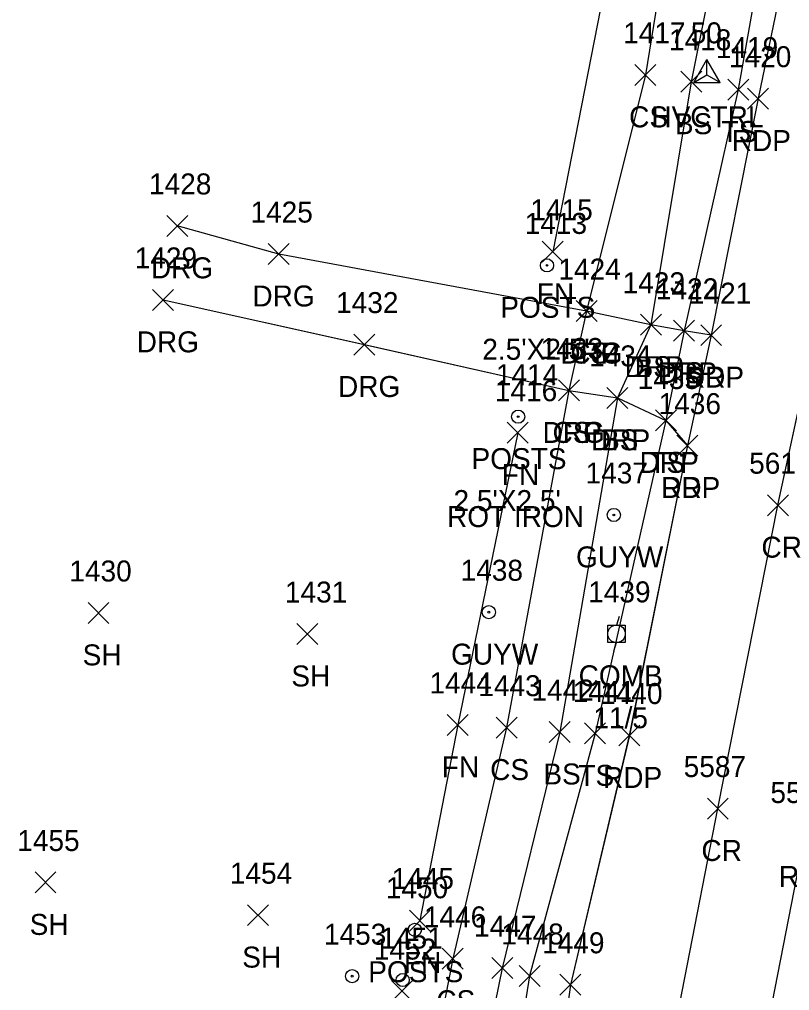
# Model space of a CAD drawing. Extents: x 1554668 to 1563881, y 831386 to 834374.
# Drawn here: x 1561703.5 to 1561777, y 833208.3 to 833300.9 of the extents above; entities that cross this region are included whole.
import ezdxf

# ---------------------------------------------------------------- set-up
doc = ezdxf.new("R2010")
doc.units = 0
for name, color, linetype in [('C_A', 7, 'Continuous'), ('C_I', 7, 'Continuous'), ('CPSM', 7, 'Continuous'), ('L_A', 7, 'Continuous'), ('L_C', 7, 'Continuous'), ('L_I', 7, 'Continuous'), ('L_TIC', 7, 'Continuous'), ('LELB', 7, 'Continuous'), ('LFNC', 7, 'Continuous'), ('LPST', 7, 'Continuous'), ('P_A', 7, 'Continuous'), ('P_I', 7, 'Continuous'), ('P_TIC', 7, 'Continuous'), ('PET', 7, 'Continuous'), ('PRC', 7, 'Continuous'), ('R_A', 7, 'Continuous'), ('R_I', 7, 'Continuous'), ('R_TIC', 7, 'Continuous'), ('RDG', 7, 'Continuous'), ('RDP', 7, 'Continuous'), ('U_A', 7, 'Continuous'), ('U_C', 7, 'Continuous'), ('U_I', 7, 'Continuous'), ('UP', 7, 'Continuous'), ('UPGW', 7, 'Continuous'), ('UWV', 7, 'Continuous')]:
    doc.layers.add(name, color=color, linetype=linetype)

msp = doc.modelspace()

# ---------------------------------------------------------------- linework, layer by layer
at = {"layer": 'CPSM'}
for p, q in [((1561767.821, 833294.896), (1561769.071, 833297.061)), ((1561770.321, 833294.896), (1561769.071, 833297.061)), ((1561769.071, 833295.618), (1561769.071, 833297.061)), ((1561767.821, 833294.896), (1561769.071, 833295.618)), ((1561767.821, 833294.896), (1561770.321, 833294.896)), ((1561769.071, 833295.618), (1561769.071, 833295.618)), ((1561769.071, 833295.618), (1561770.321, 833294.896))]:
    msp.add_line(p, q, dxfattribs=at)
at = {"layer": 'L_TIC'}
for points in [[(1561762.203, 833294.607), (1561764.203, 833296.607)], [(1561764.203, 833294.607), (1561762.203, 833296.607)], [(1561766.571, 833293.953), (1561768.571, 833295.953)], [(1561768.571, 833293.953), (1561766.571, 833295.953)], [(1561771.051, 833293.206), (1561773.051, 833295.206)], [(1561773.051, 833293.206), (1561771.051, 833295.206)], [(1561753.351, 833277.748), (1561755.351, 833279.748)], [(1561755.351, 833277.748), (1561753.351, 833279.748)], [(1561756.589, 833272.084), (1561758.589, 833274.084)], [(1561758.589, 833272.084), (1561756.589, 833274.084)], [(1561762.719, 833270.788), (1561764.719, 833272.788)], [(1561764.719, 833270.788), (1561762.719, 833272.788)], [(1561765.887, 833270.209), (1561767.887, 833272.209)], [(1561767.887, 833270.209), (1561765.887, 833272.209)], [(1561754.896, 833264.519), (1561756.896, 833266.519)], [(1561756.896, 833264.519), (1561754.896, 833266.519)], [(1561759.521, 833263.815), (1561761.521, 833265.815)], [(1561761.521, 833263.815), (1561759.521, 833265.815)], [(1561764.151, 833261.661), (1561766.151, 833263.661)], [(1561766.151, 833261.661), (1561764.151, 833263.661)], [(1561750.015, 833260.494), (1561752.015, 833262.494)], [(1561752.015, 833260.494), (1561750.015, 833262.494)], [(1561710.012, 833243.306), (1561712.012, 833245.306)], [(1561712.012, 833243.306), (1561710.012, 833245.306)], [(1561729.928, 833241.298), (1561731.928, 833243.298)], [(1561731.928, 833241.298), (1561729.928, 833243.298)], [(1561744.287, 833232.629), (1561746.287, 833234.629)], [(1561746.287, 833232.629), (1561744.287, 833234.629)], [(1561748.946, 833232.372), (1561750.946, 833234.372)], [(1561750.946, 833232.372), (1561748.946, 833234.372)], [(1561754.018, 833231.951), (1561756.018, 833233.951)], [(1561756.018, 833231.951), (1561754.018, 833233.951)], [(1561757.392, 833231.822), (1561759.392, 833233.822)], [(1561759.392, 833231.822), (1561757.392, 833233.822)], [(1561704.956, 833217.608), (1561706.956, 833219.608)], [(1561706.956, 833217.608), (1561704.956, 833219.608)], [(1561725.236, 833214.491), (1561727.236, 833216.491)], [(1561727.236, 833214.491), (1561725.236, 833216.491)], [(1561740.673, 833213.98), (1561742.673, 833215.98)], [(1561742.673, 833213.98), (1561740.673, 833215.98)], [(1561743.808, 833210.33), (1561745.808, 833212.33)], [(1561745.808, 833210.33), (1561743.808, 833212.33)], [(1561748.535, 833209.442), (1561750.535, 833211.442)], [(1561750.535, 833209.442), (1561748.535, 833211.442)], [(1561751.146, 833208.695), (1561753.146, 833210.695)], [(1561753.146, 833208.695), (1561751.146, 833210.695)], [(1561738.977, 833207.257), (1561740.977, 833209.257)], [(1561740.977, 833207.257), (1561738.977, 833209.257)]]:
    msp.add_lwpolyline(points, dxfattribs=at)
at = {"layer": 'LELB'}
for points in [[(1561770.035, 833337.792), (1561763.203, 833295.607), (1561757.589, 833273.084)], [(1561770.035, 833337.789), (1561763.203, 833295.609), (1561757.59, 833273.089)], [(1561770.035, 833337.789), (1561763.203, 833295.609), (1561757.59, 833273.089)], [(1561770.035, 833337.789), (1561763.203, 833295.609), (1561757.59, 833273.089)], [(1561775.408, 833334.066), (1561767.57, 833294.954), (1561763.719, 833271.789), (1561760.521, 833264.814), (1561755.017, 833232.947), (1561749.535, 833210.444), (1561742.76, 833177.227), (1561741.884, 833155.063), (1561737.992, 833141.16)], [(1561775.408, 833334.066), (1561767.57, 833294.954), (1561763.719, 833271.789), (1561760.521, 833264.814), (1561755.017, 833232.947), (1561749.535, 833210.444), (1561742.76, 833177.227), (1561741.884, 833155.063), (1561737.992, 833141.16)], [(1561775.408, 833334.066), (1561767.57, 833294.954), (1561763.719, 833271.789), (1561760.521, 833264.814), (1561755.017, 833232.947), (1561749.535, 833210.444), (1561742.76, 833177.227), (1561741.884, 833155.063), (1561737.992, 833141.16)], [(1561775.408, 833334.063), (1561767.571, 833294.953), (1561763.719, 833271.788), (1561760.521, 833264.815), (1561755.018, 833232.951), (1561749.535, 833210.442), (1561742.76, 833177.225), (1561741.884, 833155.061), (1561737.992, 833141.157)], [(1561778.039, 833327.932), (1561772.051, 833294.206), (1561766.887, 833271.209), (1561765.151, 833262.661), (1561758.392, 833232.822), (1561752.146, 833209.695), (1561746.841, 833176.235), (1561747.13, 833155.359), (1561743.927, 833139.533), (1561739.44, 833133.157), (1561744.939, 833126.663), (1561744.35, 833118.103), (1561739.843, 833101.573), (1561734.998, 833064.891), (1561730.679, 833041.551)], [(1561778.039, 833327.929), (1561772.052, 833294.207), (1561766.887, 833271.209), (1561765.151, 833262.665), (1561758.392, 833232.822), (1561752.146, 833209.697), (1561746.842, 833176.239), (1561747.13, 833155.358), (1561743.928, 833139.537), (1561739.44, 833133.16), (1561744.938, 833126.662), (1561744.352, 833118.106), (1561739.845, 833101.571), (1561734.998, 833064.894), (1561730.679, 833041.546)], [(1561778.039, 833327.929), (1561772.052, 833294.207), (1561766.887, 833271.209), (1561765.151, 833262.665), (1561758.392, 833232.822), (1561752.146, 833209.697), (1561746.842, 833176.239), (1561747.13, 833155.358), (1561743.928, 833139.537), (1561739.44, 833133.16), (1561744.938, 833126.662), (1561744.352, 833118.106), (1561739.845, 833101.571), (1561734.998, 833064.894), (1561730.679, 833041.546)], [(1561778.039, 833327.929), (1561772.052, 833294.207), (1561766.887, 833271.209), (1561765.151, 833262.665), (1561758.392, 833232.822), (1561752.146, 833209.697), (1561746.842, 833176.239), (1561747.13, 833155.358), (1561743.928, 833139.537), (1561739.44, 833133.16), (1561744.938, 833126.662), (1561744.352, 833118.106), (1561739.845, 833101.571), (1561734.998, 833064.894), (1561730.679, 833041.546)], [(1561755.896, 833265.519), (1561749.946, 833233.374), (1561744.808, 833211.326), (1561738.138, 833177.356), (1561738.335, 833154.49), (1561734.332, 833141.669)], [(1561755.896, 833265.519), (1561749.946, 833233.374), (1561744.808, 833211.326), (1561738.138, 833177.356), (1561738.335, 833154.49), (1561734.332, 833141.669)], [(1561755.896, 833265.519), (1561749.946, 833233.374), (1561744.808, 833211.326), (1561738.138, 833177.356), (1561738.335, 833154.49), (1561734.332, 833141.669)], [(1561755.896, 833265.519), (1561749.946, 833233.372), (1561744.808, 833211.33), (1561738.138, 833177.356), (1561738.335, 833154.49), (1561734.332, 833141.667)]]:
    msp.add_lwpolyline(points, dxfattribs=at)
at = {"layer": 'LFNC'}
for points in [[(1561764.996, 833332.946), (1561754.351, 833278.746)], [(1561764.996, 833332.946), (1561754.351, 833278.746)], [(1561764.996, 833332.946), (1561754.351, 833278.746)], [(1561764.996, 833332.944), (1561754.351, 833278.748)], [(1561751.015, 833261.495), (1561745.287, 833233.629), (1561741.673, 833214.98)], [(1561751.015, 833261.495), (1561745.287, 833233.629), (1561741.673, 833214.98)], [(1561751.015, 833261.495), (1561745.287, 833233.629), (1561741.673, 833214.98)], [(1561751.015, 833261.494), (1561745.287, 833233.629), (1561741.673, 833214.98)]]:
    msp.add_lwpolyline(points, dxfattribs=at)
at = {"layer": 'LPST'}
for centre, radius in [((1561753.809, 833277.447), 0.625), ((1561753.809, 833277.447), 0.0833), ((1561751.06, 833263.02), 0.625), ((1561751.06, 833263.02), 0.0833), ((1561741.209, 833214.1), 0.625), ((1561741.209, 833214.1), 0.0833), ((1561740.035, 833209.308), 0.625), ((1561740.035, 833209.308), 0.0833)]:
    msp.add_circle(centre, radius, dxfattribs=at)
at = {"layer": 'P_TIC'}
for points in [[(1561772.948, 833292.345), (1561774.948, 833294.345)], [(1561774.948, 833292.345), (1561772.948, 833294.345)], [(1561768.473, 833269.793), (1561770.473, 833271.793)], [(1561770.473, 833269.793), (1561768.473, 833271.793)], [(1561766.205, 833259.262), (1561768.205, 833261.262)], [(1561768.205, 833259.262), (1561766.205, 833261.262)], [(1561774.835, 833253.581), (1561776.835, 833255.581)], [(1561776.835, 833253.581), (1561774.835, 833255.581)], [(1561760.663, 833231.621), (1561762.663, 833233.621)], [(1561762.663, 833231.621), (1561760.663, 833233.621)], [(1561769.109, 833224.658), (1561771.109, 833226.658)], [(1561771.109, 833224.658), (1561769.109, 833226.658)], [(1561755.047, 833207.855), (1561757.047, 833209.855)], [(1561757.047, 833207.855), (1561755.047, 833209.855)]]:
    msp.add_lwpolyline(points, dxfattribs=at)
at = {"layer": 'PET'}
for points in [[(1561772.446, 833192.579), (1561778.438, 833223.18), (1561783.455, 833245.681), (1561787.292, 833266.873), (1561787.951, 833268.214), (1561791.576, 833284.83), (1561800.188, 833324.049), (1561804.421, 833349.461), (1561807.556, 833363.095), (1561809.846, 833376.001), (1561814.768, 833402.403)], [(1561772.446, 833192.579), (1561778.438, 833223.18), (1561783.455, 833245.681), (1561787.292, 833266.873), (1561787.951, 833268.214), (1561791.576, 833284.83), (1561800.188, 833324.049), (1561804.421, 833349.461), (1561807.556, 833363.095), (1561809.846, 833376.001), (1561814.768, 833402.403)], [(1561772.446, 833192.579), (1561778.438, 833223.18), (1561783.455, 833245.681), (1561787.292, 833266.873), (1561787.951, 833268.214), (1561791.576, 833284.83), (1561800.188, 833324.049), (1561804.421, 833349.461), (1561807.556, 833363.095), (1561809.846, 833376.001), (1561814.768, 833402.403)], [(1561772.448, 833192.582), (1561778.438, 833223.182), (1561783.456, 833245.678), (1561787.29, 833266.873), (1561787.952, 833268.21), (1561791.573, 833284.832), (1561800.187, 833324.054), (1561804.42, 833349.467), (1561807.557, 833363.104), (1561809.846, 833376.005), (1561814.767, 833402.407)], [(1561794.153, 833386.847), (1561787.73, 833353.765), (1561780.101, 833323.092), (1561773.948, 833293.345), (1561769.473, 833270.793), (1561767.205, 833260.262), (1561761.663, 833232.621), (1561756.047, 833208.855), (1561751.508, 833175.557)], [(1561794.155, 833386.844), (1561787.73, 833353.76), (1561780.101, 833323.09), (1561773.949, 833293.347), (1561769.473, 833270.791), (1561767.205, 833260.264), (1561761.664, 833232.622), (1561756.046, 833208.853), (1561751.508, 833175.556)], [(1561794.155, 833386.844), (1561787.73, 833353.76), (1561780.101, 833323.09), (1561773.949, 833293.347), (1561769.473, 833270.791), (1561767.205, 833260.264), (1561761.664, 833232.622), (1561756.046, 833208.853), (1561751.508, 833175.556)], [(1561794.155, 833386.844), (1561787.73, 833353.76), (1561780.101, 833323.09), (1561773.949, 833293.347), (1561769.473, 833270.791), (1561767.205, 833260.264), (1561761.664, 833232.622), (1561756.046, 833208.853), (1561751.508, 833175.556)]]:
    msp.add_lwpolyline(points, dxfattribs=at)
at = {"layer": 'PRC'}
for points in [[(1562300.293, 833002.635), (1562265.056, 833007.76), (1562229.752, 833015.899), (1562188.56, 833027.158), (1562163.867, 833032.834), (1562128.368, 833039.745), (1562080.008, 833048.853), (1562037.166, 833057.37), (1561989.079, 833066.767), (1561944.749, 833075.337), (1561893.656, 833085.488), (1561855.803, 833092.68), (1561805.738, 833106.779), (1561782.445, 833121.396), (1561772.46, 833130.936), (1561764.816, 833144.509), (1561760.941, 833173.068), (1561763.812, 833193.359), (1561770.109, 833225.658), (1561775.835, 833254.581), (1561787.627, 833309.043), (1561795.14, 833348.536), (1561800.21, 833371.538), (1561806.437, 833405.192)], [(1562300.297, 833002.634), (1562265.06, 833007.759), (1562229.751, 833015.899), (1562188.563, 833027.157), (1562163.87, 833032.838), (1562128.369, 833039.745), (1562080.013, 833048.851), (1562037.119, 833057.379), (1561989.031, 833066.776), (1561944.699, 833075.346), (1561893.607, 833085.494), (1561855.757, 833092.686), (1561805.685, 833106.789), (1561782.448, 833121.397), (1561772.461, 833130.936), (1561764.814, 833144.506), (1561760.941, 833173.07), (1561763.813, 833193.362), (1561770.108, 833225.654), (1561775.838, 833254.58), (1561787.632, 833309.041), (1561795.141, 833348.53), (1561800.212, 833371.537), (1561806.439, 833405.19)], [(1562300.297, 833002.634), (1562265.06, 833007.759), (1562229.751, 833015.899), (1562188.563, 833027.157), (1562163.87, 833032.838), (1562128.369, 833039.745), (1562080.013, 833048.851), (1562037.119, 833057.379), (1561989.031, 833066.776), (1561944.699, 833075.346), (1561893.607, 833085.494), (1561855.757, 833092.686), (1561805.685, 833106.789), (1561782.448, 833121.397), (1561772.461, 833130.936), (1561764.814, 833144.506), (1561760.941, 833173.07), (1561763.813, 833193.362), (1561770.108, 833225.654), (1561775.838, 833254.58), (1561787.632, 833309.041), (1561795.141, 833348.53), (1561800.212, 833371.537), (1561806.439, 833405.19)], [(1562300.297, 833002.634), (1562265.06, 833007.759), (1562229.751, 833015.899), (1562188.563, 833027.157), (1562163.87, 833032.838), (1562128.369, 833039.745), (1562080.013, 833048.851), (1562037.119, 833057.379), (1561989.031, 833066.776), (1561944.699, 833075.346), (1561893.607, 833085.494), (1561855.757, 833092.686), (1561805.685, 833106.789), (1561782.448, 833121.397), (1561772.461, 833130.936), (1561764.814, 833144.506), (1561760.941, 833173.07), (1561763.813, 833193.362), (1561770.108, 833225.654), (1561775.838, 833254.58), (1561787.632, 833309.041), (1561795.141, 833348.53), (1561800.212, 833371.537), (1561806.439, 833405.19)]]:
    msp.add_lwpolyline(points, dxfattribs=at)
at = {"layer": 'R_TIC'}
for points in [[(1561717.527, 833280.212), (1561719.527, 833282.212)], [(1561719.527, 833280.212), (1561717.527, 833282.212)], [(1561727.209, 833277.527), (1561729.209, 833279.527)], [(1561729.209, 833277.527), (1561727.209, 833279.527)], [(1561716.169, 833273.156), (1561718.169, 833275.156)], [(1561718.169, 833273.156), (1561716.169, 833275.156)], [(1561756.589, 833272.084), (1561758.589, 833274.084)], [(1561758.589, 833272.084), (1561756.589, 833274.084)], [(1561756.589, 833272.084), (1561758.589, 833274.084)], [(1561758.589, 833272.084), (1561756.589, 833274.084)], [(1561762.719, 833270.788), (1561764.719, 833272.788)], [(1561764.719, 833270.788), (1561762.719, 833272.788)], [(1561765.887, 833270.209), (1561767.887, 833272.209)], [(1561767.887, 833270.209), (1561765.887, 833272.209)], [(1561768.473, 833269.793), (1561770.473, 833271.793)], [(1561770.473, 833269.793), (1561768.473, 833271.793)], [(1561735.379, 833268.897), (1561737.379, 833270.897)], [(1561737.379, 833268.897), (1561735.379, 833270.897)], [(1561754.896, 833264.519), (1561756.896, 833266.519)], [(1561756.896, 833264.519), (1561754.896, 833266.519)], [(1561754.896, 833264.519), (1561756.896, 833266.519)], [(1561756.896, 833264.519), (1561754.896, 833266.519)], [(1561759.521, 833263.815), (1561761.521, 833265.815)], [(1561761.521, 833263.815), (1561759.521, 833265.815)], [(1561764.151, 833261.661), (1561766.151, 833263.661)], [(1561766.151, 833261.661), (1561764.151, 833263.661)], [(1561766.205, 833259.262), (1561768.205, 833261.262)], [(1561768.205, 833259.262), (1561766.205, 833261.262)]]:
    msp.add_lwpolyline(points, dxfattribs=at)
at = {"layer": 'RDG'}
for points in [[(1561757.59, 833273.089), (1561728.209, 833278.529), (1561718.527, 833281.214)], [(1561757.59, 833273.089), (1561728.209, 833278.529), (1561718.527, 833281.214)], [(1561757.59, 833273.089), (1561728.209, 833278.529), (1561718.527, 833281.214)], [(1561757.589, 833273.084), (1561728.209, 833278.527), (1561718.527, 833281.212)], [(1561717.169, 833274.156), (1561736.379, 833269.897), (1561755.896, 833265.519)], [(1561717.169, 833274.153), (1561736.378, 833269.898), (1561755.896, 833265.519)], [(1561717.169, 833274.153), (1561736.378, 833269.898), (1561755.896, 833265.519)], [(1561717.169, 833274.153), (1561736.378, 833269.898), (1561755.896, 833265.519)]]:
    msp.add_lwpolyline(points, dxfattribs=at)
at = {"layer": 'RDP'}
for points in [[(1561769.473, 833270.791), (1561766.887, 833271.209), (1561763.719, 833271.789), (1561757.59, 833273.089), (1561755.896, 833265.519), (1561760.521, 833264.814), (1561765.151, 833262.665), (1561767.205, 833260.264)], [(1561769.473, 833270.791), (1561766.887, 833271.209), (1561763.719, 833271.789), (1561757.59, 833273.089), (1561755.896, 833265.519), (1561760.521, 833264.814), (1561765.151, 833262.665), (1561767.205, 833260.264)], [(1561769.473, 833270.791), (1561766.887, 833271.209), (1561763.719, 833271.789), (1561757.59, 833273.089), (1561755.896, 833265.519), (1561760.521, 833264.814), (1561765.151, 833262.665), (1561767.205, 833260.264)], [(1561769.473, 833270.793), (1561766.887, 833271.209), (1561763.719, 833271.788), (1561757.589, 833273.084), (1561755.896, 833265.519), (1561760.521, 833264.815), (1561765.151, 833262.661), (1561767.205, 833260.262)]]:
    msp.add_lwpolyline(points, dxfattribs=at)
at = {"layer": 'UP'}
for p, q in [((1561760.691, 833243.982), (1561760.441, 833243.148)), ((1561759.607, 833241.482), (1561759.607, 833243.148)), ((1561759.607, 833243.148), (1561761.274, 833243.148)), ((1561761.274, 833243.148), (1561761.274, 833241.482)), ((1561760.441, 833242.315), (1561760.441, 833242.315)), ((1561761.274, 833241.482), (1561759.607, 833241.482)), ((1561760.191, 833240.648), (1561760.441, 833241.482))]:
    msp.add_line(p, q, dxfattribs=at)
msp.add_circle((1561760.441, 833242.315), 0.833, dxfattribs=at)
at = {"layer": 'UPGW'}
for centre, radius in [((1561760.184, 833253.649), 0.625), ((1561760.184, 833253.649), 0.0833), ((1561748.26, 833244.378), 0.625), ((1561748.26, 833244.378), 0.0833)]:
    msp.add_circle(centre, radius, dxfattribs=at)
at = {"layer": 'UWV'}
for radius in [0.625, 0.0833]:
    msp.add_circle((1561735.218, 833209.674), radius, dxfattribs=at)

# ---------------------------------------------------------------- texts
at = {"layer": 'C_A'}
msp.add_text('HVCTRL', height=2, dxfattribs=at).set_placement((1561763.764, 833290.618))
at = {"layer": 'C_I'}
msp.add_text('50', height=2, dxfattribs=at).set_placement((1561767.52, 833298.618))
at = {"layer": 'L_A'}
for s, p in [('CS', (1561761.644, 833290.607)), ('BS', (1561766.011, 833289.953)), ('TS', (1561770.461, 833289.206)), ('FN', (1561752.831, 833273.748)), ('POSTS', (1561749.352, 833272.447)), ('CS', (1561756.03, 833268.084)), ('BS', (1561762.16, 833266.788)), ('TS', (1561765.297, 833266.209)), ('CS', (1561754.337, 833260.519)), ('BS', (1561758.962, 833259.815)), ('POSTS', (1561746.604, 833258.02)), ('TS', (1561763.56, 833257.661)), ('FN', (1561749.495, 833256.494)), ('SH', (1561709.5, 833239.306)), ('SH', (1561729.416, 833237.298)), ('FN', (1561743.768, 833228.629)), ('CS', (1561748.387, 833228.372)), ('BS', (1561753.459, 833227.951)), ('TS', (1561756.801, 833227.822)), ('SH', (1561704.445, 833213.608)), ('SH', (1561724.725, 833210.491)), ('FN', (1561740.154, 833209.98)), ('POSTS', (1561736.752, 833209.1)), ('CS', (1561743.249, 833206.33))]:
    msp.add_text(s, height=2, dxfattribs=at).set_placement(p)
at = {"layer": 'L_C'}
for s, p in [("2.5'X2.5'", (1561747.636, 833268.447)), ("2.5'X2.5'", (1561744.887, 833254.02)), ('ROT IRON', (1561744.267, 833252.494))]:
    msp.add_text(s, height=2, dxfattribs=at).set_placement(p)
at = {"layer": 'L_I'}
for s, p in [('1417', (1561761.077, 833298.607)), ('1418', (1561765.445, 833297.953)), ('1419', (1561769.917, 833297.206)), ('1415', (1561752.225, 833281.748)), ('1413', (1561751.683, 833280.447)), ('1424', (1561754.896, 833276.084)), ('1423', (1561761.026, 833274.788)), ('1422', (1561764.194, 833274.209)), ('1433', (1561753.203, 833268.519)), ('1434', (1561757.828, 833267.815)), ('1414', (1561748.934, 833266.02)), ('1435', (1561762.458, 833265.661)), ('1416', (1561748.834, 833264.494)), ('1430', (1561708.232, 833247.306)), ('1431', (1561728.802, 833245.298)), ('1444', (1561742.594, 833236.629)), ('1443', (1561747.253, 833236.372)), ('1442', (1561752.325, 833235.951)), ('1441', (1561756.266, 833235.822)), ('1455', (1561703.264, 833221.608)), ('1454', (1561723.543, 833218.491)), ('1445', (1561738.98, 833217.98)), ('1450', (1561738.429, 833217.1)), ('1446', (1561742.06, 833214.33)), ('1447', (1561746.842, 833213.442)), ('1451', (1561737.909, 833212.308)), ('1448', (1561749.453, 833212.695)), ('1452', (1561737.284, 833211.257))]:
    msp.add_text(s, height=2, dxfattribs=at).set_placement(p)
at = {"layer": 'P_A'}
for s, p in [('RDP', (1561771.436, 833288.345)), ('RDP', (1561766.961, 833265.793)), ('RDP', (1561764.693, 833255.262)), ('CR', (1561774.268, 833249.581)), ('RDP', (1561759.152, 833227.621)), ('CR', (1561768.543, 833220.658)), ('RDP', (1561775.927, 833218.182))]:
    msp.add_text(s, height=2, dxfattribs=at).set_placement(p)
at = {"layer": 'P_I'}
for s, p in [('1420', (1561771.168, 833296.345)), ('1421', (1561767.347, 833273.793)), ('1436', (1561764.457, 833263.262)), ('5618', (1561773.095, 833257.581)), ('1440', (1561758.884, 833235.621)), ('5587', (1561766.85, 833228.658)), ('5586', (1561775.123, 833226.182)), ('1449', (1561753.346, 833211.855))]:
    msp.add_text(s, height=2, dxfattribs=at).set_placement(p)
at = {"layer": 'R_A'}
for s, p in [('DRG', (1561716.016, 833276.212)), ('DRG', (1561725.697, 833273.527)), ('DRG', (1561714.657, 833269.156)), ('DRG', (1561755.077, 833268.084)), ('DRP', (1561755.077, 833268.084)), ('DRP', (1561761.207, 833266.788)), ('DRP', (1561764.375, 833266.209)), ('DRP', (1561766.961, 833265.793)), ('DRG', (1561733.867, 833264.897)), ('DRG', (1561753.384, 833260.519)), ('DRP', (1561753.384, 833260.519)), ('DRP', (1561758.009, 833259.815)), ('DRP', (1561762.639, 833257.661)), ('DRP', (1561764.693, 833255.262))]:
    msp.add_text(s, height=2, dxfattribs=at).set_placement(p)
at = {"layer": 'R_I'}
for s, p in [('1428', (1561715.835, 833284.212)), ('1425', (1561725.516, 833281.527)), ('1429', (1561714.468, 833277.156)), ('1424', (1561754.896, 833276.084)), ('1424', (1561754.896, 833276.084)), ('1423', (1561761.026, 833274.788)), ('1422', (1561764.194, 833274.209)), ('1421', (1561767.347, 833273.793)), ('1432', (1561733.686, 833272.897)), ('1433', (1561753.203, 833268.519)), ('1433', (1561753.203, 833268.519)), ('1434', (1561757.828, 833267.815)), ('1435', (1561762.458, 833265.661)), ('1436', (1561764.457, 833263.262))]:
    msp.add_text(s, height=2, dxfattribs=at).set_placement(p)
at = {"layer": 'U_A'}
for s, p in [('GUYW', (1561756.577, 833248.649)), ('GUYW', (1561744.653, 833239.378)), ('COMB', (1561756.826, 833237.315))]:
    msp.add_text(s, height=2, dxfattribs=at).set_placement(p)
at = {"layer": 'U_C'}
msp.add_text('11/5', height=2, dxfattribs=at).set_placement((1561758.236, 833233.315))
at = {"layer": 'U_I'}
for s, p in [('1437', (1561757.491, 833256.649)), ('1438', (1561745.567, 833247.378)), ('1439', (1561757.74, 833245.315)), ('1453', (1561732.525, 833212.674))]:
    msp.add_text(s, height=2, dxfattribs=at).set_placement(p)

doc.saveas('drawing.dxf')
